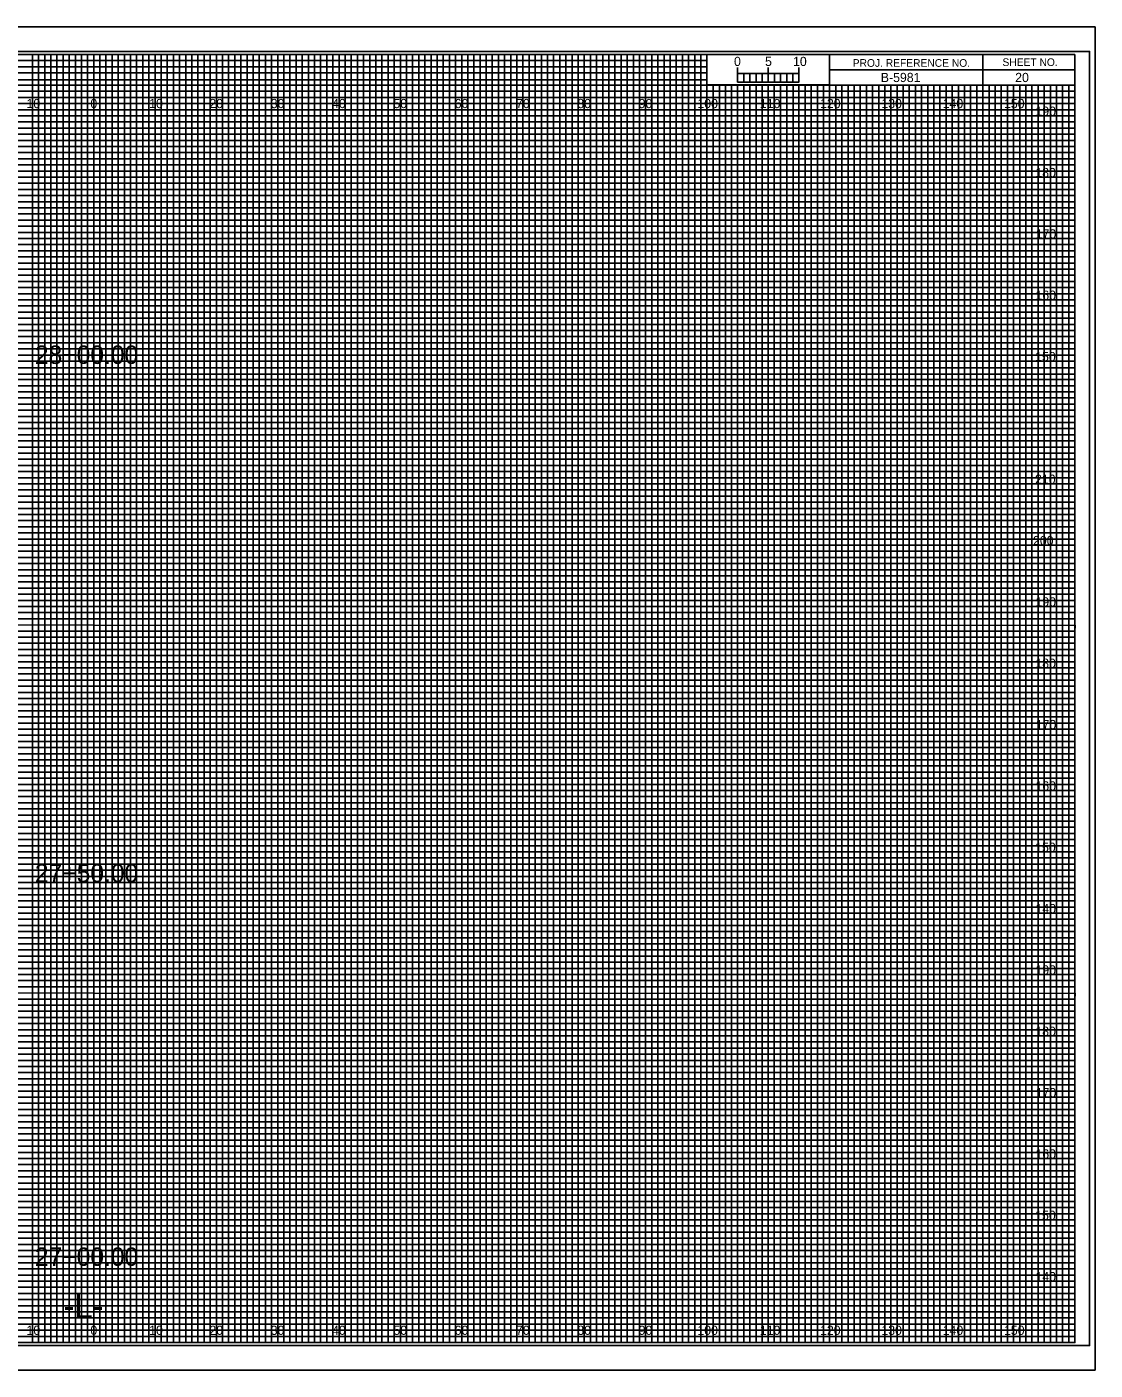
# Model space of a CAD drawing. Extents: x -13 to 323, y -5 to 4174.
# Drawn here: x 149.1 to 323.3, y 3075.5 to 3294.5 of the extents above; entities that cross this region are included whole.
import ezdxf

# ---------------------------------------------------------------- set-up
doc = ezdxf.new("R2010")
doc.units = 0
for name, color, linetype in [('Exist Cross Section Cell', 7, 'Continuous'), ('Exist XS Center Line Elevation Label', 7, 'Continuous'), ('Exist XS Ground Line', 7, 'Continuous'), ('Prop CMT Concrete Structures', 7, 'Continuous'), ('Prop CMT Guardrail Graphics', 7, 'Continuous'), ('Prop CMT Pvmt Course 1', 7, 'Continuous'), ('Prop CMT Pvmt Course 2', 7, 'Continuous'), ('Prop CMT Pvmt Course 3', 7, 'Continuous'), ('Prop CMT Pvmt Surface', 7, 'Continuous'), ('Prop CMT Shld Paved Course 1', 7, 'Continuous'), ('Prop CMT Shld Paved Course 2', 7, 'Continuous'), ('Prop CMT Shld Paved Course 3', 7, 'Continuous'), ('Prop CMT Subgrade Earthwork', 7, 'Continuous'), ('Prop XS Ditch Standard Text', 7, 'Continuous'), ('Prop XS SE Text', 7, 'Continuous'), ('Prop XS Side Slope Text', 7, 'Continuous'), ('Scratch_Level_0', 7, 'Continuous')]:
    doc.layers.add(name, color=color, linetype=linetype)

msp = doc.modelspace()

# ---------------------------------------------------------------- linework, layer by layer
at = {"layer": 'Exist XS Center Line Elevation Label'}
for points in [[(145, 3080), (155, 3080), (155, 3290), (165, 3290), (165, 3080), (175, 3080), (175, 3290), (185, 3290), (185, 3080), (195, 3080), (195, 3290), (205, 3290), (205, 3080), (215, 3080), (215, 3290), (225, 3290), (225, 3080), (235, 3080), (235, 3290), (245, 3290), (245, 3080), (255, 3080), (255, 3290), (259.93, 3290), (260, 3290), (260, 3285), (264.99, 3285), (264.99, 3080), (275, 3080), (275, 3285), (285, 3285), (285, 3080), (295, 3080), (295, 3285), (305, 3285), (305, 3080), (315, 3080), (315, 3285)], [(0, 3285), (275, 3285)], [(0, 3265), (320, 3265), (320, 3275), (0, 3275)], [(0, 3245), (320, 3245), (320, 3255), (0, 3255)], [(0, 3225), (320, 3225), (320, 3235), (0, 3235)], [(0, 3205), (320, 3205), (320, 3215), (0, 3215)], [(0, 3185), (320, 3185), (320, 3195), (0, 3195)], [(0, 3165), (320, 3165), (320, 3175), (0, 3175)], [(0, 3145), (320, 3145), (320, 3155), (0, 3155)], [(0, 3125), (320, 3125), (320, 3135), (0, 3135)], [(0, 3105), (320, 3105), (320, 3115), (0, 3115)], [(0, 3085), (320, 3085), (320, 3095), (0, 3095)]]:
    msp.add_lwpolyline(points, dxfattribs=at)
at = {"layer": 'Exist XS Ground Line'}
for p, q in [((150, 3290), (140, 3290)), ((150, 3080), (150, 3290)), ((170, 3290), (160, 3290)), ((160, 3290), (160, 3080)), ((170, 3080), (170, 3290)), ((190, 3290), (180, 3290)), ((180, 3290), (180, 3080)), ((190, 3080), (190, 3290)), ((210, 3290), (200, 3290)), ((200, 3290), (200, 3080)), ((210, 3080), (210, 3290)), ((230, 3290), (220, 3290)), ((220, 3290), (220, 3080)), ((230, 3080), (230, 3290)), ((250, 3290), (240, 3290)), ((240, 3290), (240, 3080)), ((250, 3080), (250, 3290)), ((260, 3290), (260, 3080)), ((270, 3080), (270, 3285)), ((290, 3285), (280, 3285)), ((280, 3285), (280, 3080)), ((290, 3080), (290, 3285)), ((310, 3285), (300, 3285)), ((300, 3285), (300, 3080)), ((310, 3080), (310, 3285)), ((160, 3080), (150, 3080)), ((180, 3080), (170, 3080)), ((200, 3080), (190, 3080)), ((220, 3080), (210, 3080)), ((240, 3080), (230, 3080)), ((260, 3080), (250, 3080)), ((280, 3080), (270, 3080)), ((300, 3080), (290, 3080)), ((320, 3080), (310, 3080)), ((320, 3080), (320, 3080))]:
    msp.add_line(p, q, dxfattribs=at)
for points in [[(0, 3280), (320, 3280), (320, 3270), (0, 3270)], [(0, 3260), (320, 3260), (320, 3250), (0, 3250)], [(0, 3240), (320, 3240), (320, 3230), (0, 3230)], [(0, 3220), (320, 3220), (320, 3210), (0, 3210)], [(0, 3200), (320, 3200), (320, 3190), (0, 3190)], [(0, 3180), (320, 3180), (320, 3170), (0, 3170)], [(0, 3160), (320, 3160), (320, 3150), (0, 3150)], [(0, 3140), (320, 3140), (320, 3130), (0, 3130)], [(0, 3120), (320, 3120), (320, 3110), (0, 3110)], [(0, 3100), (320, 3100), (320, 3090), (0, 3090)]]:
    msp.add_lwpolyline(points, dxfattribs=at)
at = {"layer": 'Prop CMT Pvmt Course 1'}
for p, q in [((323.3, 3294.5), (-13.4, 3294.5)), ((-13.4, 3075.5), (323.3, 3075.5))]:
    msp.add_line(p, q, dxfattribs=at)
at = {"layer": 'Prop CMT Pvmt Course 2'}
msp.add_lwpolyline([(-13.4, 3075.5), (323.3, 3075.5), (323.3, 3294.5), (-13.4, 3294.5)], close=True, dxfattribs=at)
at = {"layer": 'Prop CMT Pvmt Course 3'}
msp.add_lwpolyline([(-10.8, 3079.5), (322.4, 3079.5), (322.4, 3290.5), (-10.8, 3290.5)], close=True, dxfattribs=at)
at = {"layer": 'Prop CMT Shld Paved Course 1'}
for p, q in [((305, 3290), (305, 3285)), ((305, 3285), (305, 3290)), ((280, 3287.5), (280, 3285)), ((320, 3287.49), (280, 3287.49)), ((280, 3285), (320, 3285))]:
    msp.add_line(p, q, dxfattribs=at)
for points in [[(320, 3290), (0, 3290), (0, 3080), (320, 3080)], [(280, 3290), (260, 3290), (260, 3285.03), (280, 3285.03)], [(320, 3290), (280, 3290), (280, 3285), (320, 3285)]]:
    msp.add_lwpolyline(points, close=True, dxfattribs=at)
at = {"layer": 'Prop CMT Shld Paved Course 2'}
for p, q in [((267, 3285), (266.01, 3285)), ((266.01, 3285), (266.01, 3080)), ((267, 3080), (267, 3285)), ((269, 3285), (268, 3285)), ((268, 3285), (268, 3080)), ((269, 3080), (269, 3285)), ((266.01, 3080), (265, 3080)), ((268, 3080), (267, 3080))]:
    msp.add_line(p, q, dxfattribs=at)
for points in [[(150, 3080), (151, 3080), (151, 3290), (152, 3290), (152, 3080)], [(152, 3080), (153, 3080), (153, 3290), (154, 3290), (154, 3080)], [(155, 3080), (156, 3080), (156, 3290), (157, 3290), (157, 3080)], [(157, 3080), (158, 3080), (158, 3290), (159, 3290), (159, 3080)], [(160, 3080), (161, 3080), (161, 3290), (162, 3290), (162, 3080)], [(162, 3080), (163, 3080), (163, 3290), (164, 3290), (164, 3080)], [(165, 3080), (166, 3080), (166, 3290), (167, 3290), (167, 3080)], [(167, 3080), (168, 3080), (168, 3290), (169, 3290), (169, 3080)], [(170, 3080), (171, 3080), (171, 3290), (172, 3290), (172, 3080)], [(172, 3080), (173, 3080), (173, 3290), (174, 3290), (174, 3080)], [(175, 3080), (176, 3080), (176, 3290), (177, 3290), (177, 3080)], [(177, 3080), (178, 3080), (178, 3290), (179, 3290), (179, 3080)], [(180, 3080), (181, 3080), (181, 3290), (182, 3290), (182, 3080)], [(182, 3080), (183, 3080), (183, 3290), (184, 3290), (184, 3080)], [(185, 3080), (186, 3080), (186, 3290), (187, 3290), (187, 3080)], [(187, 3080), (188, 3080), (188, 3290), (189, 3290), (189, 3080)], [(190, 3080), (191, 3080), (191, 3290), (192, 3290), (192, 3080)], [(192, 3080), (193, 3080), (193, 3290), (194, 3290), (194, 3080)], [(195, 3080), (196, 3080), (196, 3290), (197, 3290), (197, 3080)], [(197, 3080), (198, 3080), (198, 3290), (199, 3290), (199, 3080)], [(200, 3080), (201, 3080), (201, 3290), (202, 3290), (202, 3080)], [(202, 3080), (203, 3080), (203, 3290), (204, 3290), (204, 3080)], [(205, 3080), (206, 3080), (206, 3290), (207, 3290), (207, 3080)], [(207, 3080), (208, 3080), (208, 3290), (209, 3290), (209, 3080)], [(210, 3080), (211, 3080), (211, 3290), (212, 3290), (212, 3080)], [(212, 3080), (213, 3080), (213, 3290), (214, 3290), (214, 3080)], [(215, 3080), (216, 3080), (216, 3290), (217, 3290), (217, 3080)], [(217, 3080), (218, 3080), (218, 3290), (219, 3290), (219, 3080)], [(220, 3080), (221, 3080), (221, 3290), (222, 3290), (222, 3080)], [(222, 3080), (223, 3080), (223, 3290), (224, 3290), (224, 3080)], [(225, 3080), (226, 3080), (226, 3290), (227, 3290), (227, 3080)], [(227, 3080), (228, 3080), (228, 3290), (229, 3290), (229, 3080)], [(230, 3080), (231, 3080), (231, 3290), (232, 3290), (232, 3080)], [(232, 3080), (233, 3080), (233, 3290), (234, 3290), (234, 3080)], [(235, 3080), (236, 3080), (236, 3290), (237, 3290), (237, 3080)], [(237, 3080), (238, 3080), (238, 3290), (239, 3290), (239, 3080)], [(240, 3080), (241, 3080), (241, 3290), (242, 3290), (242, 3080)], [(242, 3080), (243, 3080), (243, 3290), (244, 3290), (244, 3080)], [(245, 3080), (246, 3080), (246, 3290), (247, 3290), (247, 3080)], [(247, 3080), (248, 3080), (248, 3290), (249, 3290), (249, 3080)], [(250, 3080), (251, 3080), (251, 3290), (252, 3290), (252, 3080)], [(252, 3080), (253, 3080), (253, 3290), (254, 3290), (254, 3080)], [(255, 3080), (256, 3080), (256, 3290), (257, 3290), (257, 3080)], [(257, 3080), (258, 3080), (258, 3290), (259, 3290), (259, 3080)], [(260, 3080), (261, 3080), (261, 3285), (262.02, 3285), (262.02, 3080)], [(262, 3080), (263, 3080), (263, 3285), (263.99, 3285), (263.99, 3080)], [(270, 3080), (270.98, 3080), (270.98, 3285), (272, 3285), (272, 3080)], [(272, 3080), (273, 3080), (273, 3285), (274.05, 3285), (274.05, 3080)], [(275, 3080), (276, 3080), (276, 3285), (277, 3285), (277, 3080)], [(277, 3080), (278, 3080), (278, 3285), (279, 3285), (279, 3080)], [(280, 3080), (281, 3080), (281, 3285), (282, 3285), (282, 3080)], [(282, 3080), (283, 3080), (283, 3285), (284, 3285), (284, 3080)], [(285, 3080), (286, 3080), (286, 3285), (287, 3285), (287, 3080)], [(287, 3080), (288, 3080), (288, 3285), (289, 3285), (289, 3080)], [(290, 3080), (291, 3080), (291, 3285), (292, 3285), (292, 3080)], [(292, 3080), (293, 3080), (293, 3285), (294, 3285), (294, 3080)], [(295, 3080), (296, 3080), (296, 3285), (297, 3285), (297, 3080)], [(297, 3080), (298, 3080), (298, 3285), (299, 3285), (299, 3080)], [(300, 3080), (301, 3080), (301, 3285), (302, 3285), (302, 3080)], [(302, 3080), (303, 3080), (303, 3285), (304, 3285), (304, 3080)], [(305, 3080), (306, 3080), (306, 3285), (307, 3285), (307, 3080)], [(307, 3080), (308, 3080), (308, 3285), (309, 3285), (309, 3080)], [(310, 3080), (311, 3080), (311, 3285), (312, 3285), (312, 3080)], [(312, 3080), (313, 3080), (313, 3285), (314, 3285), (314, 3080)], [(315, 3080), (316, 3080), (316, 3285), (317, 3285), (317, 3080)], [(317, 3080), (318, 3080), (318, 3285), (319, 3285), (319, 3080)]]:
    msp.add_lwpolyline(points, dxfattribs=at)
at = {"layer": 'Prop CMT Shld Paved Course 3'}
for p, q in [((265, 3285.49), (265, 3287.9)), ((265, 3286.9), (265, 3287.9)), ((270, 3285.49), (270, 3287.9)), ((275, 3285.49), (275, 3287.9)), ((275, 3286.9), (275, 3287.9))]:
    msp.add_line(p, q, dxfattribs=at)
for points in [[(275, 3286.9), (265, 3286.9), (265, 3285.49), (275, 3285.49)], [(265, 3286.9), (266, 3286.9), (266, 3285.49), (265, 3285.49)], [(267, 3286.9), (268, 3286.9), (268, 3285.49), (267, 3285.49)], [(269, 3286.9), (270, 3286.9), (270, 3285.49), (269, 3285.49)], [(271, 3286.9), (272, 3286.9), (272, 3285.49), (271, 3285.49)], [(273, 3286.9), (274, 3286.9), (274, 3285.49), (273, 3285.49)]]:
    msp.add_lwpolyline(points, close=True, dxfattribs=at)
at = {"layer": 'Prop CMT Subgrade Earthwork'}
for p, q in [((150, 3080), (150, 3290)), ((160, 3080), (160, 3290)), ((170, 3080), (170, 3290)), ((180, 3080), (180, 3290)), ((190, 3080), (190, 3290)), ((200, 3080), (200, 3290)), ((210, 3080), (210, 3290)), ((220, 3080), (220, 3290)), ((230, 3080), (230, 3290)), ((240, 3080), (240, 3290)), ((250, 3080), (250, 3290)), ((260, 3080), (260, 3284.69)), ((270, 3080), (270, 3284.69)), ((280, 3080), (280, 3284.69)), ((290, 3080), (290, 3284.69)), ((300, 3080), (300, 3284.69)), ((310, 3080), (310, 3284.69)), ((0, 3280), (320, 3280)), ((0, 3270), (320, 3270)), ((0, 3260), (320, 3260)), ((0, 3250), (320, 3250)), ((0, 3240), (320, 3240)), ((0, 3230), (320, 3230)), ((0, 3220), (320, 3220)), ((0, 3210), (320, 3210)), ((0, 3200), (320, 3200)), ((0, 3190), (320, 3190)), ((0, 3180), (320, 3180)), ((0, 3170), (320, 3170)), ((0, 3160), (320, 3160)), ((0, 3150), (320, 3150)), ((0, 3140), (320, 3140)), ((0, 3130), (320, 3130)), ((0, 3120), (320, 3120)), ((0, 3110), (320, 3110)), ((0, 3100), (320, 3100)), ((0, 3090), (320, 3090))]:
    msp.add_line(p, q, dxfattribs=at)
at = {"layer": 'Scratch_Level_0'}
for p, q in [((0, 3289), (260, 3289)), ((260, 3287.98), (0, 3287.98)), ((260, 3289), (260, 3287.98)), ((0, 3287), (260, 3287)), ((260, 3285.89), (0, 3285.89)), ((260, 3287), (260, 3285.89)), ((0, 3284), (320, 3284))]:
    msp.add_line(p, q, dxfattribs=at)
for points in [[(0, 3283), (270, 3283), (320, 3283), (320, 3282), (0, 3282)], [(0, 3281), (320, 3281), (320, 3279), (0, 3279)], [(0, 3278), (320, 3278), (320, 3277), (0, 3276.98)], [(0, 3276), (320, 3276), (320, 3274), (0, 3274)], [(0, 3273), (320, 3273), (320, 3272), (0, 3272)], [(0, 3271), (320, 3271), (320, 3269), (0, 3269)], [(0, 3268), (320, 3268), (320, 3267), (0, 3267)], [(0, 3266), (320, 3266), (320, 3264), (0, 3264)], [(0, 3263), (320, 3263), (320, 3262), (0, 3262)], [(0, 3261), (320, 3261), (320, 3259), (0, 3259)], [(0, 3258), (320, 3258), (320, 3257), (0, 3257)], [(0, 3256), (320, 3256), (320, 3253.95), (320, 3253), (320, 3252), (0, 3252)], [(0, 3254), (320, 3254), (320, 3253), (0, 3253)], [(0, 3251), (320, 3251), (320, 3249), (0, 3249.03)], [(0, 3249.03), (320, 3249), (320, 3248), (0, 3248)], [(0, 3247), (320, 3247), (320, 3246), (0, 3246)], [(0, 3244), (320, 3244), (320, 3243), (0, 3243)], [(0, 3242), (320, 3242), (320, 3241), (0, 3241)], [(-0.07, 3238.89), (320, 3238.89), (320, 3237.88), (-0.07, 3237.88)], [(0, 3237), (320, 3237), (320, 3236), (0, 3236)], [(0, 3234), (320, 3234), (320, 3233), (0, 3233)], [(0, 3232), (320, 3232), (320, 3231), (0, 3231)], [(0, 3229), (320, 3229), (320, 3228), (0, 3228)], [(0, 3227), (320, 3227), (320, 3226), (0, 3226)], [(0, 3224), (320, 3224), (320, 3223), (0, 3223)], [(0, 3222), (320, 3222), (320, 3221), (0, 3221)], [(0, 3219), (320, 3219), (319.99, 3217.98), (0, 3218)], [(0, 3217), (320, 3217), (320, 3216), (0, 3216)], [(0, 3214), (320, 3214), (320, 3213), (0, 3213)], [(0, 3212), (320, 3212), (320, 3211), (0, 3211)], [(0, 3209), (320, 3209), (320, 3208), (0, 3208)], [(0, 3207), (320, 3207), (320, 3206), (0, 3206)], [(0, 3204), (320, 3204), (320, 3203), (0, 3203)], [(0, 3202), (320, 3202), (320, 3201), (0, 3201)], [(0, 3199), (320, 3199), (320, 3198), (0, 3198)], [(0, 3196.99), (320.07, 3196.91), (320, 3196), (0, 3196)], [(0, 3194), (320, 3194), (320, 3193), (0, 3193)], [(0, 3192), (320, 3192), (320, 3191), (0, 3191)], [(0, 3189), (320, 3189), (320, 3188), (0, 3188)], [(0, 3187), (320, 3187), (320, 3186), (0, 3186)], [(0, 3184), (320, 3184), (320, 3183), (0, 3183)], [(0, 3182), (320, 3182), (320, 3181), (0, 3181)], [(0, 3179), (320, 3179), (320, 3178), (0, 3178)], [(0, 3177), (320, 3177), (320, 3176), (0, 3176)], [(0, 3174), (320, 3174), (320, 3173), (0, 3173)], [(0, 3172), (320, 3172), (320, 3171), (0, 3171)], [(0, 3169), (320, 3169), (320, 3168), (0, 3168)], [(0, 3167), (320, 3167), (320, 3166), (0, 3166)], [(0, 3164), (320, 3164), (320, 3163), (0, 3163)], [(0, 3162), (320, 3162), (320, 3161), (0, 3161)], [(0, 3159), (320, 3159), (319.99, 3157.98), (0, 3158)], [(0, 3157), (320, 3157), (320, 3156), (0, 3156)], [(0, 3154), (320, 3154), (320, 3153), (0, 3153)], [(0, 3152), (320, 3152), (320, 3151), (0, 3151)], [(0, 3149), (320, 3149), (320, 3148), (0, 3148)], [(0, 3147), (320, 3147), (320, 3146), (0, 3146)], [(0, 3144), (320, 3144), (320, 3143), (0, 3143)], [(0, 3142), (320, 3142), (320, 3141), (0, 3141)], [(0, 3139), (320, 3139), (320, 3138), (0, 3138)], [(0, 3136.99), (320.07, 3136.91), (320, 3136), (0, 3136)], [(0, 3134), (320, 3134), (320, 3133), (0, 3133)], [(0, 3132), (320, 3132), (320, 3131), (0, 3131)], [(0, 3129), (320, 3129), (320, 3128), (0, 3128)], [(0, 3127), (320, 3127), (320, 3126), (0, 3126)], [(0, 3124), (320, 3124), (320, 3123), (0, 3123)], [(0, 3122), (320, 3122), (320, 3121), (0, 3121)], [(0, 3119), (320, 3119), (320, 3118), (0, 3118)], [(0, 3117), (320, 3117), (320, 3116), (0, 3116)], [(0, 3114), (320, 3114), (320, 3113), (0, 3113)], [(0, 3112), (320, 3112), (320, 3111), (0, 3111)], [(0, 3109), (320, 3109), (320, 3108), (0, 3108)], [(0, 3107), (320, 3107), (320, 3106), (0, 3106)], [(0, 3104), (320, 3104), (320, 3103), (0, 3103)], [(0, 3102), (320, 3102), (320, 3101), (0, 3101)], [(0, 3099), (320, 3099), (320, 3098), (0, 3098)], [(0, 3097), (320, 3097), (320, 3096), (0, 3096)], [(0, 3094), (320, 3094), (320, 3093), (0, 3093)], [(0, 3092), (320, 3092), (320, 3091), (0, 3091)], [(0, 3089), (320, 3089), (320, 3088), (0, 3088)], [(0, 3087), (320, 3087), (320, 3086), (0, 3086)], [(0, 3084), (320, 3084), (320, 3083), (0, 3083)], [(0, 3082), (320, 3082), (320, 3081), (0, 3081)]]:
    msp.add_lwpolyline(points, dxfattribs=at)

# ---------------------------------------------------------------- texts
at = {"layer": 'Exist Cross Section Cell'}
for s, p in [('10', (149.04, 3281.25)), ('0', (159.45, 3281.25)), ('0', (159.45, 3281.25)), ('10', (169.04, 3281.25)), ('20', (178.86, 3281.25)), ('30', (188.86, 3281.25)), ('40', (198.86, 3281.25)), ('50', (208.86, 3281.25)), ('60', (218.86, 3281.25)), ('70', (228.86, 3281.25)), ('80', (238.86, 3281.25)), ('90', (248.86, 3281.25)), ('100', (258.44, 3281.25)), ('110', (268.62, 3281.25)), ('120', (278.44, 3281.25)), ('130', (288.44, 3281.25)), ('140', (298.44, 3281.25)), ('150', (308.44, 3281.25)), ('10', (149.04, 3081.25)), ('0', (159.45, 3081.25)), ('0', (159.45, 3081.25)), ('10', (169.04, 3081.25)), ('20', (178.86, 3081.25)), ('30', (188.86, 3081.25)), ('40', (198.86, 3081.25)), ('50', (208.86, 3081.25)), ('60', (218.86, 3081.25)), ('70', (228.86, 3081.25)), ('80', (238.86, 3081.25)), ('90', (248.86, 3081.25)), ('100', (258.44, 3081.25)), ('110', (268.62, 3081.25)), ('120', (278.44, 3081.25)), ('130', (288.44, 3081.25)), ('140', (298.44, 3081.25)), ('150', (308.44, 3081.25))]:
    msp.add_text(s, height=1.5, dxfattribs=at).set_placement(p)
at = {"layer": 'Prop CMT Concrete Structures'}
for s, p in [('28+00.00', (150.41, 3239.55)), ('27+50.00', (150.41, 3155.03)), ('27+00.00', (150.41, 3092.5))]:
    msp.add_text(s, height=3, dxfattribs=at).set_placement(p)
at = {"layer": 'Prop CMT Guardrail Graphics'}
for s, p in [('190', (313.57, 3280)), ('180', (313.55, 3270)), ('170', (313.61, 3260)), ('160', (313.57, 3250)), ('150', (313.52, 3240)), ('210', (313.5, 3220)), ('200', (313.17, 3210)), ('190', (313.57, 3200)), ('180', (313.55, 3190)), ('170', (313.61, 3180)), ('160', (313.57, 3170)), ('150', (313.52, 3160)), ('140', (313.57, 3150)), ('190', (313.57, 3140)), ('180', (313.55, 3130)), ('170', (313.61, 3120)), ('160', (313.57, 3110)), ('150', (313.52, 3100)), ('140', (313.57, 3090))]:
    msp.add_text(s, height=1.5, dxfattribs=at).set_placement(p)
at = {"layer": 'Prop CMT Pvmt Surface'}
for s, p in [('5', (269.47, 3288.12)), ('10', (274.04, 3288.12))]:
    msp.add_text(s, height=1.5, dxfattribs=at).set_placement(p)
at = {"layer": 'Prop CMT Shld Paved Course 1'}
for s, p in [('SHEET NO.', (308.19, 3288.12)), ('PROJ. REFERENCE NO.', (283.77, 3287.99))]:
    msp.add_text(s, height=1.25, dxfattribs=at).set_placement(p)
at = {"layer": 'Prop CMT Shld Paved Course 3'}
msp.add_text('0', height=1.5, dxfattribs=at).set_placement((264.41, 3288.12))
at = {"layer": 'Prop XS Ditch Standard Text'}
msp.add_text('-L-', height=4, dxfattribs=at).set_placement((155.06, 3084))
at = {"layer": 'Prop XS SE Text'}
msp.add_text(' B-5981', height=1.5, dxfattribs=at).set_placement((287.79, 3285.5))
at = {"layer": 'Prop XS Side Slope Text'}
msp.add_text('20', height=1.5, dxfattribs=at).set_placement((310.26, 3285.5))

doc.saveas('drawing.dxf')
